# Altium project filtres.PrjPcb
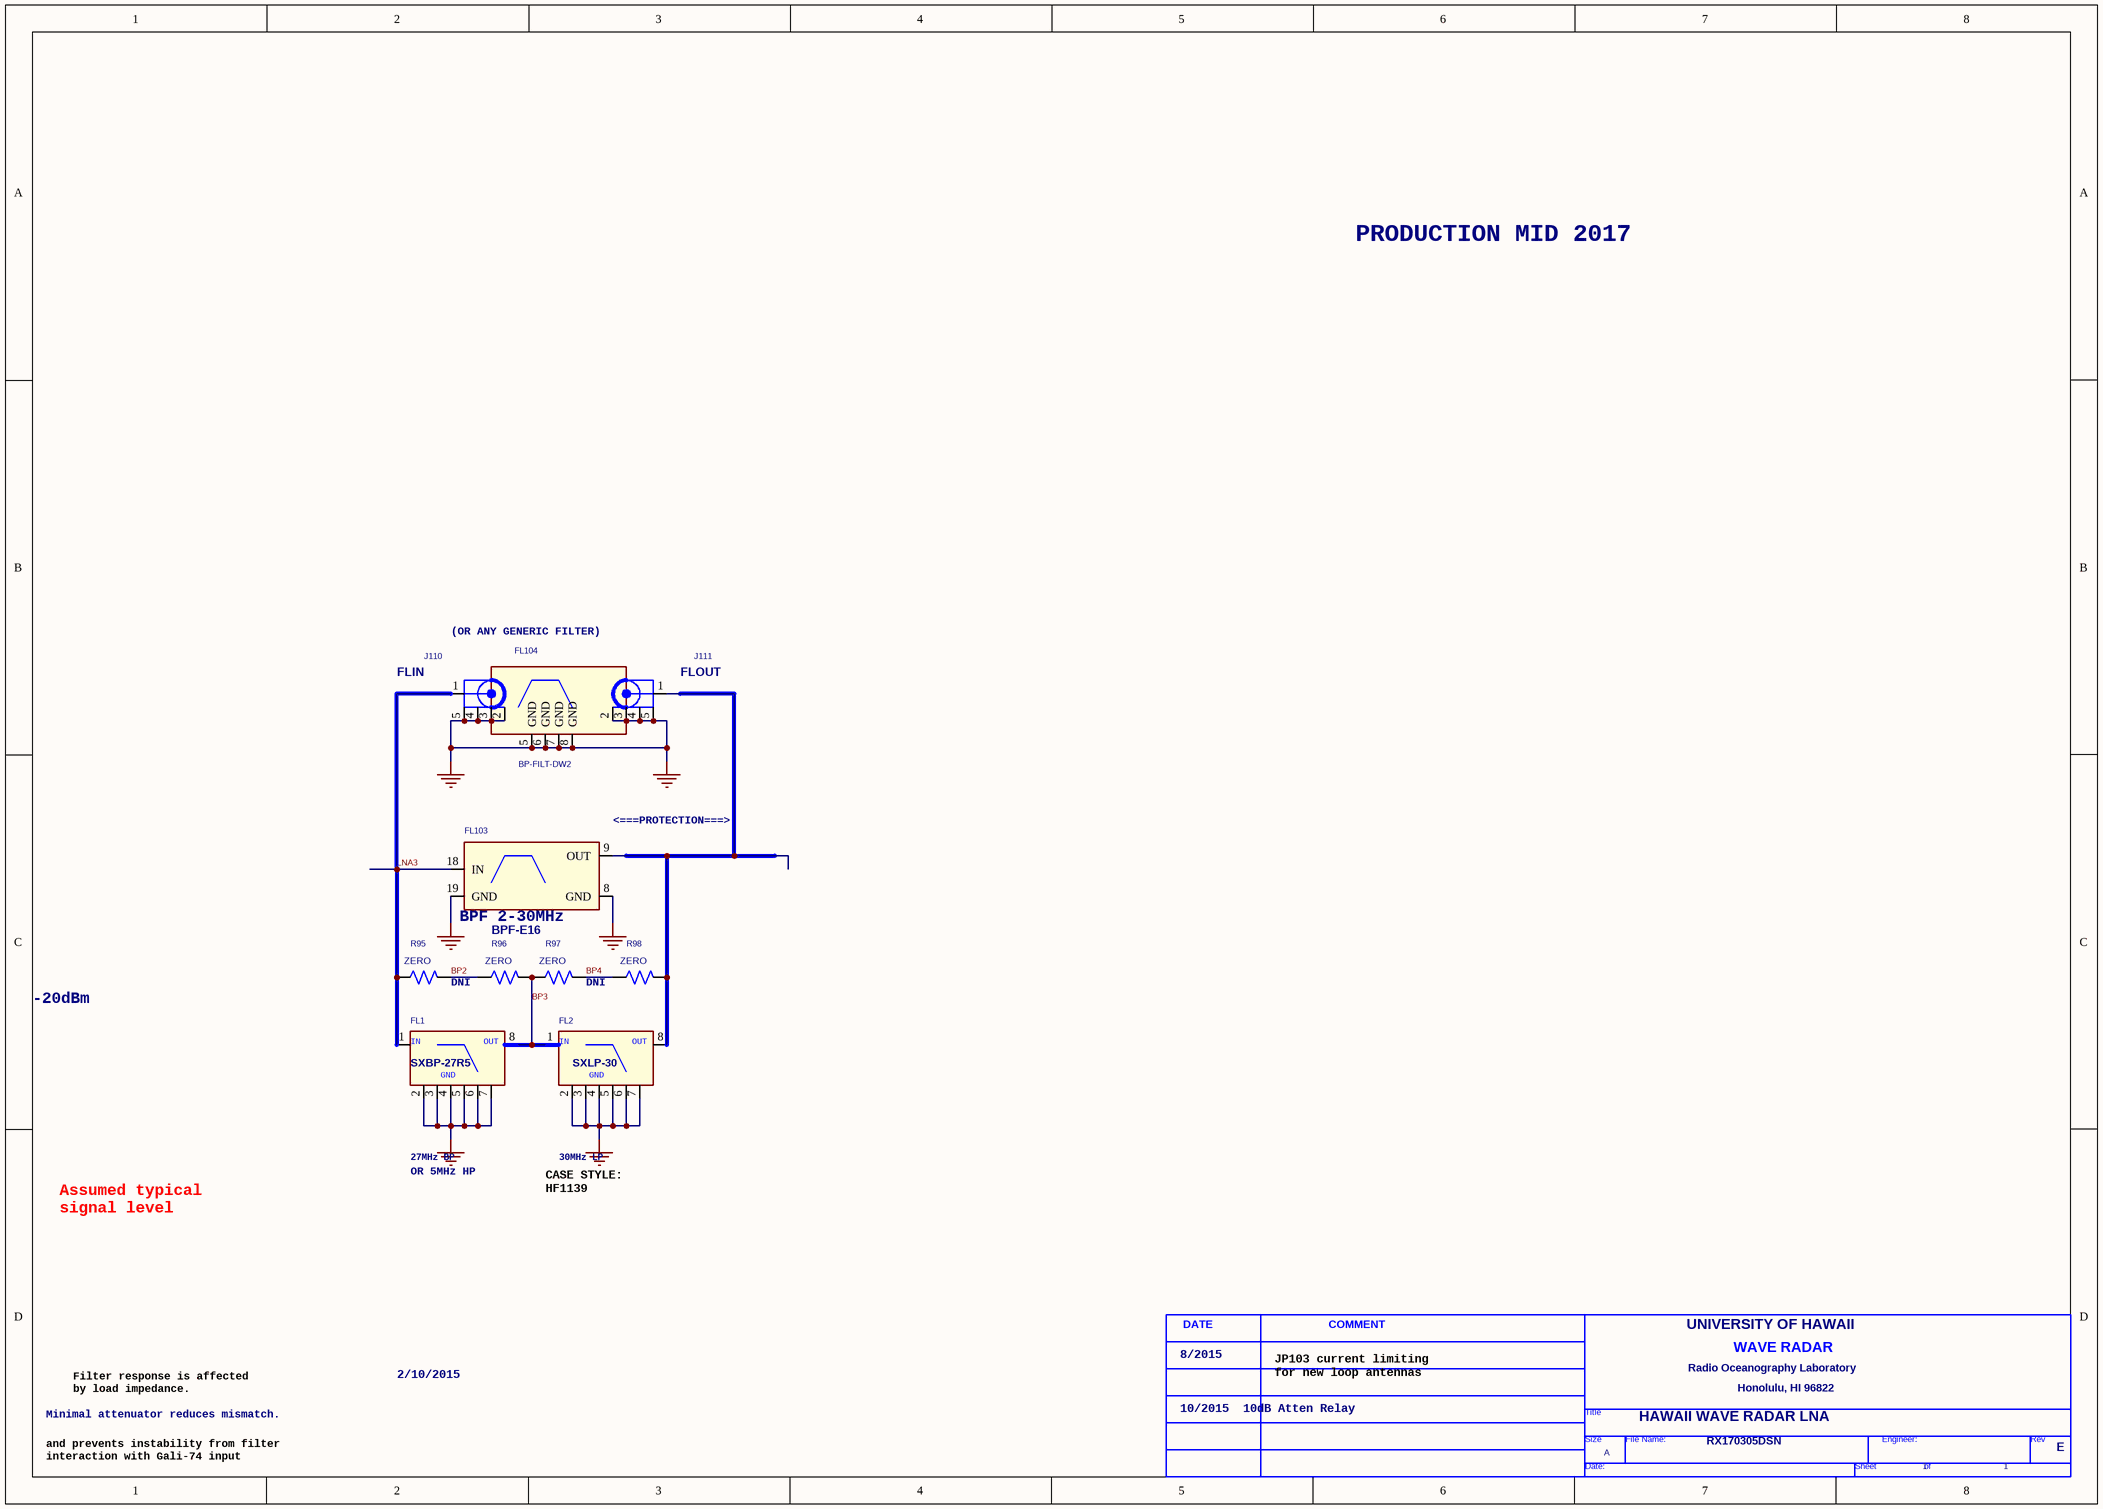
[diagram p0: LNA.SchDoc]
1 sheet, 12 parts. Net scope: global (net labels, ports and power ports of the same name join across sheets).
Board file: filtres CRX-8-21.PcbDoc

## Sheet LNA.SchDoc
size A3; Organization: Altium Limited; Address1: L3, 12a Rodborough Rd; Address2: Frenchs Forest; Address3: NSW; Address4: Australia 2086

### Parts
(Parts that share a designator on the sheet are numbered #1, #2 ... from top to bottom, then left to right.)
*#1  DCB  (value not drawn)  (graphical)
*#2  Doc: RX170305DSN  RevCode: E  Title: HAWAII WAVE RADAR LNA  OrgName: UNIVERSITY OF HAWAII  OrgAddr1: Radio Oceanography Laboratory  OrgAddr3: Honolulu, HI 96822  Page Size: A  Page Number: 1  (hidden comment: HWRadar)  (graphical)
FL1  SXBP-27R5  [HF1149]
FL2  SXLP-30  [HF1149]
FL103  BPF-E16  [HR1176]
FL104  BP-FILT-DW2  [BP-FILTER-DW]
J110  FLIN  [SMA]
J111  FLOUT  [SMA]
R95  ZERO  [R1206]
R96  ZERO  [R1206]
R97  ZERO  [R1206]
R98  ZERO  [R1206]

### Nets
GND: FL1.2(GND) FL1.3(GND) FL1.4(GND) FL1.5(GND) FL1.6(GND) FL1.7(GND) FL2.2(GND) FL2.3(GND) FL2.4(GND) FL2.5(GND) FL2.6(GND) FL2.7(GND) FL103.1(GND) FL103.2(GND) FL103.3(GND) FL103.4(GND) FL103.5(GND) FL103.6(GND) FL103.7(GND) FL103.8(GND) FL103.10(GND) FL103.11(GND) FL103.12(GND) FL103.13(GND) FL103.14(GND) FL103.15(GND) FL103.16(GND) FL103.17(GND) FL103.19(GND) FL103.20(GND) FL104.5(GND) FL104.6(GND) FL104.7(GND) FL104.8(GND) J110.2(SHIELD) J110.3(SHIELD) J110.4(SHIELD) J110.5(SHIELD) J111.2(SHIELD) J111.3(SHIELD) J111.4(SHIELD) J111.5(SHIELD)
BP2: R95.2 R96.1
BP3: FL1.8(OUT) FL2.1(IN) R96.2 R97.1
BP4: R97.2 R98.1
LNA3: FL1.1(IN) FL103.18(IN) J110.1(CENTER) R95.1
NetFL2_8: FL2.8(OUT) FL103.9(OUT) J111.1(CENTER) R98.2

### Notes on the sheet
- PRODUCTION MID 2017
- (OR ANY GENERIC FILTER)
- (near FL103) <===PROTECTION===>
- (near FL103) BPF 2-30MHz
- DNI
- -20dBm
- 27MHz BP
- OR 5MHz HP
- 30MHz LP
- Assumed typical
  signal level
- CASE STYLE:
  HF1139
- 2/10/2015
- (near *#1) 8/2015
- JP103 current limiting
  for new loop antennas
- Minimal attenuator reduces mismatch.
- Filter response is affected
  by load impedance.
- 10/2015  10dB Atten Relay
- and prevents instability from filter
  interaction with Gali-74 input

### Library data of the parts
*#2 = HWRadar: Engineer:: <ENG>; OrgAddr2: 2525 Correa Road
FL1 = LP FILTER_1: MFR: MCI; MFR PART: SXBP-27R5+; DK Stock: MiniCircuits
FL2 = LP FILTER_1: MFR: MCI; MFR PART: SXLP-30+; DK Stock: MiniCircuits
FL103 = BPF-E16: MFR: MCI; MFR PART: BPF-E16+; DK Stock: MiniCircuits
FL104 = BP-FILTER-DW_1
J110 J111 = SMA-4G: MFR PART: 133-3701-211; MFR: Cinch Connectivity Solutions Johnson; DK Stock: J539-ND
R95-R98 = R1206: MFR PART: RC1206JR-070RL; MFR: Yageo; DK Stock: 311-0.0ERCT-ND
